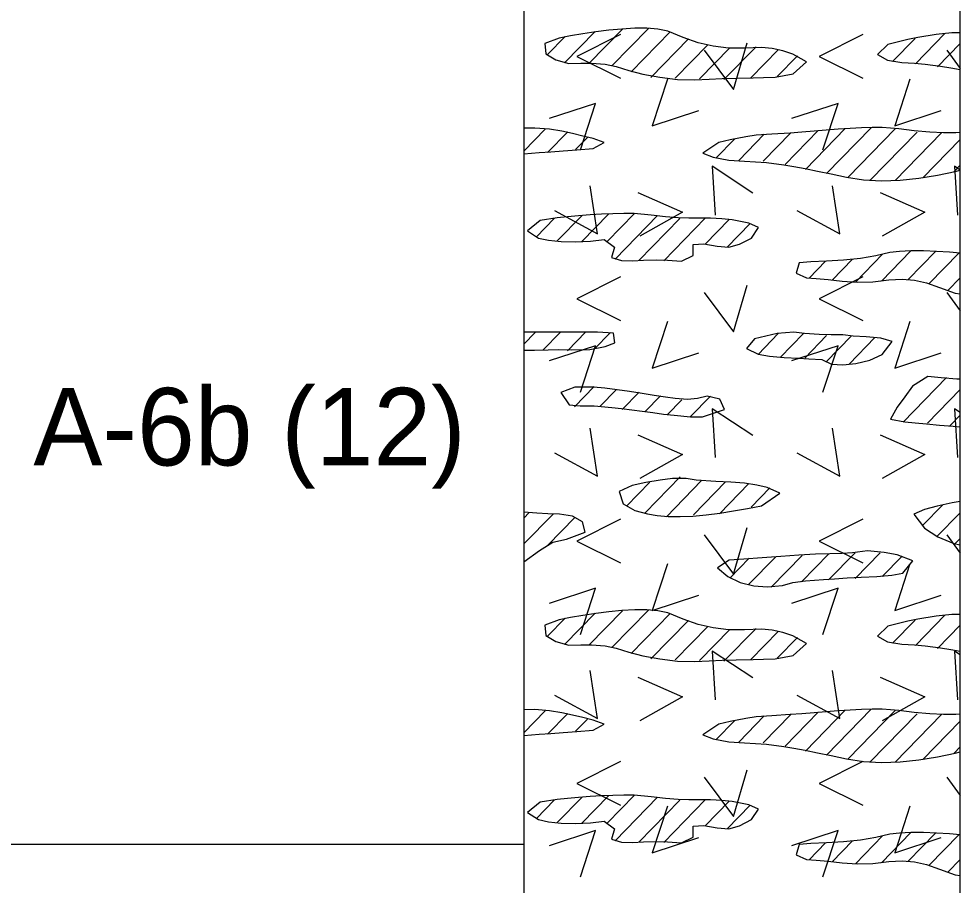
# Model space of a CAD drawing. Extents: x -0.01 to 0.83, y -0.63 to 1.27.
# Drawn here: x 0.7524 to 0.8333, y 1.001 to 1.0754 of the extents above; entities that cross this region are included whole.
import ezdxf

# ---------------------------------------------------------------- set-up
doc = ezdxf.new("R2010")
doc.units = 0

msp = doc.modelspace()

# ---------------------------------------------------------------- linework, layer by layer
for points in [[(0, 0), (0.833332, 0), (0.833332, 1.274997), (0, 1.274997)], [(0, 0), (0.833332, 0), (0.833332, 1.274997), (0, 1.274997)], [(0, 0), (0.833332, 0), (0.833332, 1.274997), (0, 1.274997)], [(0, 0), (0.833332, 0), (0.833332, 1.274997), (0, 1.274997)], [(0, 0), (0.833332, 0), (0.833332, 1.274997), (0, 1.274997)], [(0.798854, 1.073778), (0.797634, 1.073317), (0.797728, 1.072422), (0.798587, 1.071898), (0.799696, 1.071602), (0.800742, 1.071612), (0.801652, 1.071626), (0.802809, 1.071543), (0.803766, 1.071335), (0.804856, 1.070986), (0.80606, 1.070689), (0.807509, 1.070415), (0.809046, 1.070229), (0.810517, 1.070199), (0.811769, 1.070256), (0.812889, 1.070297), (0.814075, 1.070332), (0.815527, 1.070372), (0.816416, 1.070398), (0.817445, 1.07043), (0.818967, 1.070703), (0.820111, 1.071739), (0.818963, 1.072408), (0.818099, 1.072676), (0.817169, 1.072872), (0.816265, 1.072977), (0.814793, 1.072918), (0.813435, 1.072921), (0.812104, 1.073071), (0.810802, 1.073373), (0.809527, 1.073834), (0.808198, 1.074383), (0.807356, 1.074543), (0.806403, 1.074617), (0.805364, 1.074618), (0.804267, 1.074558), (0.803138, 1.074449), (0.802006, 1.074304), (0.800896, 1.074136), (0.799837, 1.073957)], [(0.832629, 1.074225), (0.831261, 1.074087), (0.829688, 1.073822), (0.828826, 1.073648), (0.82712, 1.073238), (0.826226, 1.072369), (0.827084, 1.071877), (0.828308, 1.071691), (0.829408, 1.071625), (0.830335, 1.071536), (0.831655, 1.071354), (0.832526, 1.071211), (0.833332, 1.071069), (0.833332, 1.074217)], [(0.795832, 1.063822), (0.797147, 1.063932), (0.798141, 1.064005), (0.799224, 1.064082), (0.800394, 1.064167), (0.80179, 1.064289), (0.802748, 1.064804), (0.801793, 1.065146), (0.800911, 1.06536), (0.800027, 1.06558), (0.79909, 1.065787), (0.798029, 1.065952), (0.79677, 1.066048), (0.795832, 1.066027)], [(0.828162, 1.061574), (0.82978, 1.061743), (0.831374, 1.061995), (0.832902, 1.062306), (0.833332, 1.062411), (0.833332, 1.065652), (0.832951, 1.065619), (0.831885, 1.06564), (0.830714, 1.065693), (0.829383, 1.065796), (0.828069, 1.065965), (0.826619, 1.066084), (0.825765, 1.066086), (0.824843, 1.066059), (0.823868, 1.066008), (0.822856, 1.06594), (0.82182, 1.06586), (0.820774, 1.065776), (0.819735, 1.065693), (0.818715, 1.065618), (0.817148, 1.065523), (0.815785, 1.065431), (0.814914, 1.065297), (0.813574, 1.065023), (0.812595, 1.06481), (0.811206, 1.063892), (0.812105, 1.06353), (0.813452, 1.063284), (0.814789, 1.063193), (0.816678, 1.06309), (0.818181, 1.06289), (0.819046, 1.062744), (0.820004, 1.062565), (0.821067, 1.062351), (0.82225, 1.062099), (0.823565, 1.061808), (0.825013, 1.061582), (0.826559, 1.061512)], [(0.797084, 1.056592), (0.797938, 1.056414), (0.799042, 1.056302), (0.800285, 1.056268), (0.801555, 1.056323), (0.802742, 1.056477), (0.803614, 1.055815), (0.803377, 1.054918), (0.804221, 1.054648), (0.805167, 1.054629), (0.806129, 1.054685), (0.807202, 1.054716), (0.808182, 1.054685), (0.809387, 1.054612), (0.81037, 1.055077), (0.81038, 1.056024), (0.811296, 1.056087), (0.812442, 1.0559), (0.813463, 1.055793), (0.814379, 1.056049), (0.815394, 1.056592), (0.816006, 1.057504), (0.81517, 1.057877), (0.813738, 1.058153), (0.812849, 1.058246), (0.811872, 1.058304), (0.810001, 1.058306), (0.809104, 1.058324), (0.808002, 1.058398), (0.806784, 1.058555), (0.805305, 1.058686), (0.804427, 1.058699), (0.803488, 1.058683), (0.802511, 1.058642), (0.801521, 1.05858), (0.80054, 1.058502), (0.799593, 1.058411), (0.798702, 1.058312), (0.797221, 1.058089), (0.796138, 1.057211)], [(0.832407, 1.055373), (0.831293, 1.055438), (0.830172, 1.055475), (0.829096, 1.055477), (0.828115, 1.055438), (0.827281, 1.05535), (0.826083, 1.05505), (0.824762, 1.054824), (0.823296, 1.054687), (0.821831, 1.054605), (0.820509, 1.054546), (0.819505, 1.054447), (0.819224, 1.053583), (0.820125, 1.053164), (0.820967, 1.053112), (0.821997, 1.053013), (0.823181, 1.052883), (0.824476, 1.052794), (0.825838, 1.052819), (0.82719, 1.052984), (0.828356, 1.05305), (0.829402, 1.052969), (0.830435, 1.052736), (0.831559, 1.052345), (0.832909, 1.051856), (0.833332, 1.051779), (0.833332, 1.055298)], [(0.795832, 1.04696), (0.796757, 1.04695), (0.797925, 1.04697), (0.798816, 1.047008), (0.799915, 1.046965), (0.801515, 1.047009), (0.802823, 1.047266), (0.803666, 1.047585), (0.80354, 1.048424), (0.802165, 1.048509), (0.795832, 1.048509)], [(0.818216, 1.046315), (0.819444, 1.046257), (0.820325, 1.046216), (0.821453, 1.046149), (0.822286, 1.045735), (0.82324, 1.04569), (0.824378, 1.045796), (0.825554, 1.046084), (0.826624, 1.046588), (0.82749, 1.047685), (0.826513, 1.047989), (0.825239, 1.048089), (0.82413, 1.048153), (0.823236, 1.048259), (0.822257, 1.048278), (0.821211, 1.048302), (0.819948, 1.048394), (0.819024, 1.048509), (0.817611, 1.04837), (0.815663, 1.047926), (0.814958, 1.047088), (0.815983, 1.046599), (0.816947, 1.046423)], [(0.833053, 1.044461), (0.831709, 1.044573), (0.830539, 1.044674), (0.829246, 1.043854), (0.828567, 1.04294), (0.827924, 1.042053), (0.827345, 1.041027), (0.828579, 1.040801), (0.829451, 1.0407), (0.830451, 1.040604), (0.831549, 1.040508), (0.832716, 1.040412), (0.833332, 1.04036), (0.833332, 1.044452)], [(0.800664, 1.042158), (0.801881, 1.042152), (0.803392, 1.042023), (0.804229, 1.041927), (0.805103, 1.041817), (0.806004, 1.041699), (0.806919, 1.041578), (0.807838, 1.04146), (0.808747, 1.04135), (0.810142, 1.041209), (0.811186, 1.04122), (0.812223, 1.041565), (0.81308, 1.04185), (0.812673, 1.042752), (0.811597, 1.043), (0.810749, 1.042801), (0.809892, 1.042718), (0.808847, 1.042799), (0.807995, 1.04291), (0.807033, 1.043055), (0.805997, 1.043218), (0.804922, 1.043385), (0.803843, 1.043542), (0.802797, 1.043674), (0.801817, 1.043766), (0.800202, 1.043775), (0.799007, 1.043302), (0.79974, 1.04226)], [(0.812326, 1.035653), (0.810635, 1.035772), (0.809773, 1.035905), (0.808601, 1.035912), (0.807553, 1.035768), (0.806321, 1.035569), (0.805133, 1.035326), (0.804031, 1.034805), (0.804359, 1.033744), (0.805363, 1.033177), (0.806466, 1.032879), (0.807303, 1.032728), (0.80824, 1.032652), (0.80926, 1.032643), (0.810349, 1.032694), (0.811489, 1.032797), (0.812666, 1.032944), (0.813863, 1.033127), (0.815063, 1.03334), (0.816252, 1.033574), (0.81783, 1.034655), (0.816735, 1.035154), (0.815852, 1.035357), (0.814797, 1.035514), (0.813609, 1.035617)], [(0.832654, 1.03384), (0.831362, 1.033531), (0.830275, 1.033256), (0.829339, 1.032863), (0.830265, 1.031663), (0.831418, 1.030899), (0.832792, 1.030321), (0.833332, 1.030222), (0.833332, 1.033931)], [(0.795832, 1.028744), (0.79719, 1.029734), (0.798312, 1.030436), (0.799509, 1.030707), (0.801112, 1.031308), (0.800861, 1.032193), (0.800021, 1.032668), (0.798893, 1.032863), (0.797908, 1.032892), (0.796943, 1.032949), (0.795832, 1.033032)], [(0.825375, 1.029687), (0.824078, 1.029537), (0.823187, 1.02948), (0.822142, 1.029456), (0.820907, 1.029419), (0.819474, 1.029327), (0.817918, 1.029207), (0.816318, 1.029087), (0.814751, 1.028994), (0.813476, 1.028894), (0.812472, 1.028254), (0.813366, 1.027493), (0.814436, 1.026989), (0.815612, 1.0267), (0.816749, 1.026595), (0.818067, 1.026707), (0.818959, 1.026983), (0.820031, 1.027127), (0.821573, 1.027249), (0.82253, 1.027307), (0.823615, 1.027366), (0.824832, 1.027427), (0.826183, 1.027493), (0.827451, 1.027601), (0.828416, 1.027777), (0.829268, 1.028832), (0.827909, 1.029348), (0.826788, 1.029548)], [(0.798854, 1.023779), (0.797634, 1.023318), (0.797728, 1.022422), (0.798587, 1.021898), (0.799696, 1.021602), (0.800742, 1.021612), (0.801652, 1.021626), (0.802809, 1.021543), (0.803766, 1.021335), (0.804856, 1.020986), (0.80606, 1.020689), (0.807509, 1.020415), (0.809046, 1.020229), (0.810517, 1.020199), (0.811769, 1.020256), (0.812889, 1.020297), (0.814075, 1.020332), (0.815527, 1.020373), (0.816416, 1.020398), (0.817445, 1.02043), (0.818967, 1.020704), (0.820111, 1.021739), (0.818963, 1.022408), (0.818099, 1.022676), (0.817169, 1.022872), (0.816265, 1.022977), (0.814793, 1.022918), (0.813435, 1.022921), (0.812104, 1.023071), (0.810802, 1.023374), (0.809527, 1.023834), (0.808198, 1.024383), (0.807356, 1.024543), (0.806403, 1.024618), (0.805364, 1.024618), (0.804267, 1.024558), (0.803138, 1.024449), (0.802006, 1.024304), (0.800896, 1.024136), (0.799837, 1.023957)], [(0.832629, 1.024225), (0.831261, 1.024087), (0.829688, 1.023822), (0.828826, 1.023649), (0.82712, 1.023238), (0.826226, 1.022369), (0.827084, 1.021877), (0.828308, 1.021691), (0.829408, 1.021625), (0.830335, 1.021537), (0.831655, 1.021354), (0.832526, 1.021211), (0.833332, 1.021069), (0.833332, 1.024217)], [(0.795832, 1.013822), (0.797147, 1.013932), (0.798141, 1.014005), (0.799224, 1.014082), (0.800394, 1.014167), (0.80179, 1.01429), (0.802748, 1.014804), (0.801793, 1.015146), (0.800911, 1.01536), (0.800027, 1.01558), (0.79909, 1.015787), (0.798029, 1.015952), (0.79677, 1.016048), (0.795832, 1.016027)], [(0.828162, 1.011574), (0.82978, 1.011743), (0.831374, 1.011995), (0.832902, 1.012307), (0.833332, 1.012411), (0.833332, 1.015652), (0.832951, 1.015619), (0.831885, 1.01564), (0.830714, 1.015693), (0.829383, 1.015796), (0.828069, 1.015965), (0.826619, 1.016084), (0.825765, 1.016086), (0.824843, 1.016059), (0.823868, 1.016008), (0.822856, 1.01594), (0.82182, 1.01586), (0.820774, 1.015776), (0.819735, 1.015693), (0.818715, 1.015618), (0.817148, 1.015523), (0.815785, 1.015431), (0.814914, 1.015297), (0.813574, 1.015023), (0.812595, 1.01481), (0.811206, 1.013892), (0.812105, 1.01353), (0.813452, 1.013284), (0.814789, 1.013193), (0.816678, 1.01309), (0.818181, 1.01289), (0.819046, 1.012744), (0.820004, 1.012565), (0.821067, 1.012351), (0.82225, 1.012099), (0.823565, 1.011808), (0.825013, 1.011582), (0.826559, 1.011512)], [(0.797084, 1.006592), (0.797938, 1.006414), (0.799042, 1.006302), (0.800285, 1.006268), (0.801555, 1.006323), (0.802742, 1.006477), (0.803614, 1.005816), (0.803377, 1.004918), (0.804221, 1.004648), (0.805167, 1.004629), (0.806129, 1.004685), (0.807202, 1.004716), (0.808182, 1.004685), (0.809387, 1.004612), (0.81037, 1.005077), (0.81038, 1.006024), (0.811296, 1.006087), (0.812442, 1.0059), (0.813463, 1.005794), (0.814379, 1.006049), (0.815394, 1.006592), (0.816006, 1.007504), (0.81517, 1.007877), (0.813738, 1.008153), (0.812849, 1.008246), (0.811872, 1.008304), (0.810001, 1.008306), (0.809104, 1.008325), (0.808002, 1.008398), (0.806784, 1.008555), (0.805305, 1.008686), (0.804427, 1.008699), (0.803488, 1.008683), (0.802511, 1.008642), (0.801521, 1.00858), (0.80054, 1.008502), (0.799593, 1.008411), (0.798702, 1.008312), (0.797221, 1.008089), (0.796138, 1.007211)], [(0.832407, 1.005373), (0.831293, 1.005438), (0.830172, 1.005475), (0.829096, 1.005477), (0.828115, 1.005438), (0.827281, 1.00535), (0.826083, 1.00505), (0.824762, 1.004824), (0.823296, 1.004687), (0.821831, 1.004605), (0.820509, 1.004546), (0.819505, 1.004447), (0.819224, 1.003583), (0.820125, 1.003164), (0.820967, 1.003112), (0.821997, 1.003013), (0.823181, 1.002883), (0.824476, 1.002794), (0.825838, 1.00282), (0.82719, 1.002984), (0.828356, 1.00305), (0.829402, 1.002969), (0.830435, 1.002736), (0.831559, 1.002345), (0.832909, 1.001856), (0.833332, 1.001779), (0.833332, 1.005298)]]:
    msp.add_lwpolyline(points, close=True)
for points in [[(0.795832, 1.220831), (0.795832, -0.621832)], [(0.833332, -0.621832), (0.833332, 1.138431)], [(0.801419, 1.071582), (0.804299, 1.074534)], [(0.806532, 1.074609), (0.803395, 1.071395)], [(0.799375, 1.073914), (0.797863, 1.072364)], [(0.799328, 1.071653), (0.801951, 1.07434)], [(0.804125, 1.074079), (0.800375, 1.072204), (0.804125, 1.070329)], [(0.805059, 1.070886), (0.808397, 1.074307)], [(0.809973, 1.073709), (0.806747, 1.070403)], [(0.824958, 1.074079), (0.821208, 1.072204), (0.824958, 1.070329)], [(0.827512, 1.071761), (0.82945, 1.073746)], [(0.832025, 1.074174), (0.829489, 1.071574)], [(0.811636, 1.073201), (0.808841, 1.070337)], [(0.813527, 1.072925), (0.810936, 1.070271)], [(0.811342, 1.072738), (0.813842, 1.069363), (0.815029, 1.073363)], [(0.813032, 1.070205), (0.815789, 1.073031)], [(0.831379, 1.071298), (0.833332, 1.073299)], [(0.815342, 1.07036), (0.817681, 1.072756)], [(0.817605, 1.070465), (0.819344, 1.072248)], [(0.832175, 1.072738), (0.833332, 1.071177)], [(0.833327, 1.071082), (0.833332, 1.071087)], [(0.808181, 1.070248), (0.806868, 1.066248), (0.810868, 1.06756)], [(0.829014, 1.070248), (0.827702, 1.066248), (0.831702, 1.06756)], [(0.800689, 1.064167), (0.802002, 1.068167), (0.798002, 1.066855)], [(0.821523, 1.064167), (0.822835, 1.068167), (0.818835, 1.066855)], [(0.797655, 1.065935), (0.795832, 1.064066)], [(0.799604, 1.065719), (0.797864, 1.063937)], [(0.814303, 1.063259), (0.816499, 1.065509)], [(0.816395, 1.06319), (0.818789, 1.065644)], [(0.818285, 1.062914), (0.821137, 1.065836)], [(0.820035, 1.062494), (0.823455, 1.065999)], [(0.825691, 1.066076), (0.82184, 1.062131)], [(0.827752, 1.065976), (0.823702, 1.061827)], [(0.829644, 1.065702), (0.825565, 1.061523)], [(0.831735, 1.065632), (0.827743, 1.061542)], [(0.801295, 1.06524), (0.800268, 1.064188)], [(0.813923, 1.065082), (0.812354, 1.063475)], [(0.833332, 1.065055), (0.830118, 1.061762)], [(0.815512, 1.060441), (0.812012, 1.062754), (0.812262, 1.058566)], [(0.832808, 1.062306), (0.833332, 1.062842)], [(0.833332, 1.062432), (0.832845, 1.062754), (0.833095, 1.058566)], [(0.798466, 1.058959), (0.802154, 1.056959), (0.801529, 1.061084)], [(0.8193, 1.058959), (0.822987, 1.056959), (0.822362, 1.061084)], [(0.805617, 1.060504), (0.809456, 1.058821), (0.805806, 1.056759)], [(0.82645, 1.060504), (0.83029, 1.058821), (0.826639, 1.056759)], [(0.798444, 1.058275), (0.796912, 1.056705)], [(0.79871, 1.056335), (0.800849, 1.058526)], [(0.800827, 1.056291), (0.803111, 1.058632)], [(0.805344, 1.058706), (0.802987, 1.056291)], [(0.80367, 1.05478), (0.807321, 1.05852)], [(0.805714, 1.054661), (0.809241, 1.058275)], [(0.811418, 1.058292), (0.807854, 1.05464)], [(0.811407, 1.056068), (0.81348, 1.058193)], [(0.815282, 1.057827), (0.813313, 1.055809)], [(0.824327, 1.052804), (0.82666, 1.055194)], [(0.829094, 1.055477), (0.826565, 1.052885)], [(0.828848, 1.053012), (0.831218, 1.05544)], [(0.833245, 1.055305), (0.830651, 1.052646)], [(0.820346, 1.05315), (0.821763, 1.054602)], [(0.822335, 1.052976), (0.824076, 1.05476)], [(0.804125, 1.053246), (0.800375, 1.051371), (0.804125, 1.049496)], [(0.824958, 1.053246), (0.821208, 1.051371), (0.824958, 1.049496)], [(0.833332, 1.05318), (0.832267, 1.052089)], [(0.811342, 1.051905), (0.813842, 1.04853), (0.815029, 1.05253)], [(0.832175, 1.051905), (0.833332, 1.050344)], [(0.808181, 1.049414), (0.806868, 1.045414), (0.810868, 1.046727)], [(0.829014, 1.049414), (0.827702, 1.045414), (0.831702, 1.046727)], [(0.801161, 1.048515), (0.799593, 1.046907)], [(0.795832, 1.047479), (0.796808, 1.048479)], [(0.798985, 1.048497), (0.797473, 1.046948)], [(0.803281, 1.048474), (0.801883, 1.047042)], [(0.817701, 1.048373), (0.815961, 1.04659)], [(0.819878, 1.048391), (0.817852, 1.046314)], [(0.821854, 1.048202), (0.819972, 1.046274)], [(0.824002, 1.048191), (0.821778, 1.045912)], [(0.826007, 1.048033), (0.823783, 1.045754)], [(0.800689, 1.043334), (0.802002, 1.047334), (0.798002, 1.046022)], [(0.821523, 1.043334), (0.822835, 1.047334), (0.818835, 1.046022)], [(0.832167, 1.044587), (0.828441, 1.04077)], [(0.801877, 1.043814), (0.800195, 1.04209)], [(0.803798, 1.04357), (0.80237, 1.042107)], [(0.805745, 1.043352), (0.804291, 1.041862)], [(0.80758, 1.043019), (0.806268, 1.041674)], [(0.811876, 1.042996), (0.810165, 1.041243)], [(0.833332, 1.043568), (0.830521, 1.040689)], [(0.809414, 1.042686), (0.808159, 1.0414)], [(0.815512, 1.039608), (0.812012, 1.041921), (0.812262, 1.037733)], [(0.833332, 1.041355), (0.832451, 1.040453)], [(0.833332, 1.041599), (0.832845, 1.041921), (0.833095, 1.037733)], [(0.798466, 1.038126), (0.802154, 1.036126), (0.801529, 1.040251)], [(0.805617, 1.039671), (0.809456, 1.037987), (0.805806, 1.035925)], [(0.8193, 1.038126), (0.822987, 1.036126), (0.822362, 1.040251)], [(0.82645, 1.039671), (0.83029, 1.037987), (0.826639, 1.035925)], [(0.804649, 1.033536), (0.806674, 1.035611)], [(0.806256, 1.032969), (0.809278, 1.036066)], [(0.80809, 1.032636), (0.811113, 1.035734)], [(0.810409, 1.0328), (0.813175, 1.035634)], [(0.812643, 1.032877), (0.815181, 1.035477)], [(0.815361, 1.033448), (0.816987, 1.035114)], [(0.830098, 1.031874), (0.831838, 1.033657)], [(0.796303, 1.03299), (0.795832, 1.032507)], [(0.798338, 1.032862), (0.795832, 1.030294)], [(0.797862, 1.030162), (0.800229, 1.032587)], [(0.804125, 1.032413), (0.800375, 1.030538), (0.804125, 1.028663)], [(0.824958, 1.032413), (0.821208, 1.030538), (0.824958, 1.028663)], [(0.831305, 1.0309), (0.833332, 1.032975)], [(0.811342, 1.031072), (0.813842, 1.027697), (0.815029, 1.031697)], [(0.832175, 1.031072), (0.833332, 1.02951)], [(0.832854, 1.030273), (0.833332, 1.030762)], [(0.815145, 1.026796), (0.817482, 1.029191)], [(0.817092, 1.026579), (0.819744, 1.029295)], [(0.819696, 1.027034), (0.822034, 1.029431)], [(0.822015, 1.027197), (0.824297, 1.029535)], [(0.824306, 1.027332), (0.826445, 1.029524)], [(0.826625, 1.027496), (0.828336, 1.029249)], [(0.808181, 1.028581), (0.806868, 1.024581), (0.810868, 1.025894)], [(0.815192, 1.029058), (0.813538, 1.027362)], [(0.829014, 1.028581), (0.827702, 1.024581), (0.831702, 1.025894)], [(0.800689, 1.022501), (0.802002, 1.026501), (0.798002, 1.025188)], [(0.821523, 1.022501), (0.822835, 1.026501), (0.818835, 1.025188)], [(0.799328, 1.021653), (0.801951, 1.024341)], [(0.801419, 1.021582), (0.804299, 1.024534)], [(0.806532, 1.024609), (0.803395, 1.021395)], [(0.805059, 1.020886), (0.808397, 1.024307)], [(0.799375, 1.023914), (0.797863, 1.022364)], [(0.809973, 1.023709), (0.806747, 1.020403)], [(0.827512, 1.021761), (0.82945, 1.023746)], [(0.832025, 1.024174), (0.829489, 1.021574)], [(0.811636, 1.023201), (0.808841, 1.020337)], [(0.813527, 1.022926), (0.810936, 1.020271)], [(0.813032, 1.020205), (0.815789, 1.023031)], [(0.815342, 1.02036), (0.817681, 1.022756)], [(0.831379, 1.021299), (0.833332, 1.023299)], [(0.817605, 1.020465), (0.819344, 1.022248)], [(0.815512, 1.018775), (0.812012, 1.021087), (0.812262, 1.0169)], [(0.833332, 1.020766), (0.832845, 1.021087), (0.833095, 1.0169)], [(0.833327, 1.021082), (0.833332, 1.021087)], [(0.798466, 1.017292), (0.802154, 1.015292), (0.801529, 1.019417)], [(0.8193, 1.017292), (0.822987, 1.015292), (0.822362, 1.019417)], [(0.805617, 1.018837), (0.809456, 1.017154), (0.805806, 1.015092)], [(0.82645, 1.018837), (0.83029, 1.017154), (0.826639, 1.015092)], [(0.797655, 1.015935), (0.795832, 1.014066)], [(0.799604, 1.015719), (0.797864, 1.013937)], [(0.814303, 1.013259), (0.816499, 1.015509)], [(0.816395, 1.01319), (0.818789, 1.015644)], [(0.818285, 1.012914), (0.821137, 1.015836)], [(0.820035, 1.012494), (0.823455, 1.015999)], [(0.825691, 1.016077), (0.82184, 1.012131)], [(0.827752, 1.015976), (0.823702, 1.011827)], [(0.829644, 1.015702), (0.825565, 1.011524)], [(0.831735, 1.015632), (0.827743, 1.011542)], [(0.801295, 1.01524), (0.800268, 1.014188)], [(0.813923, 1.015082), (0.812354, 1.013475)], [(0.833332, 1.015055), (0.830118, 1.011763)], [(0.832808, 1.012306), (0.833332, 1.012842)], [(0.804125, 1.01158), (0.800375, 1.009705), (0.804125, 1.00783)], [(0.824958, 1.01158), (0.821208, 1.009705), (0.824958, 1.00783)], [(0.811342, 1.010238), (0.813842, 1.006863), (0.815029, 1.010863)], [(0.832175, 1.010238), (0.833332, 1.008677)], [(0.798444, 1.008275), (0.796912, 1.006705)], [(0.79871, 1.006335), (0.800849, 1.008527)], [(0.800827, 1.006291), (0.803111, 1.008632)], [(0.805344, 1.008707), (0.802987, 1.006291)], [(0.80367, 1.00478), (0.807321, 1.00852)], [(0.805714, 1.004661), (0.809241, 1.008275)], [(0.811418, 1.008292), (0.807854, 1.00464)], [(0.811407, 1.006069), (0.81348, 1.008193)], [(0.808181, 1.007748), (0.806868, 1.003748), (0.810868, 1.00506)], [(0.815282, 1.007827), (0.813313, 1.005809)], [(0.829014, 1.007748), (0.827702, 1.003748), (0.831702, 1.00506)], [(0.800689, 1.001667), (0.802002, 1.005667), (0.798002, 1.004355)], [(0.821523, 1.001667), (0.822835, 1.005667), (0.818835, 1.004355)], [(0.824327, 1.002805), (0.82666, 1.005194)], [(0.829094, 1.005477), (0.826565, 1.002885)], [(0.828848, 1.003012), (0.831218, 1.00544)], [(0.833245, 1.005305), (0.830651, 1.002646)], [(0.749999, 1.004498), (0.795832, 1.004498)], [(0.820346, 1.00315), (0.821763, 1.004602)], [(0.822335, 1.002976), (0.824076, 1.00476)], [(0.833332, 1.00318), (0.832267, 1.002089)]]:
    msp.add_lwpolyline(points)

# ---------------------------------------------------------------- texts
msp.add_text('A-6b (12)', height=0.0066667).set_placement((0.753677, 1.03704))

doc.saveas('drawing.dxf')
